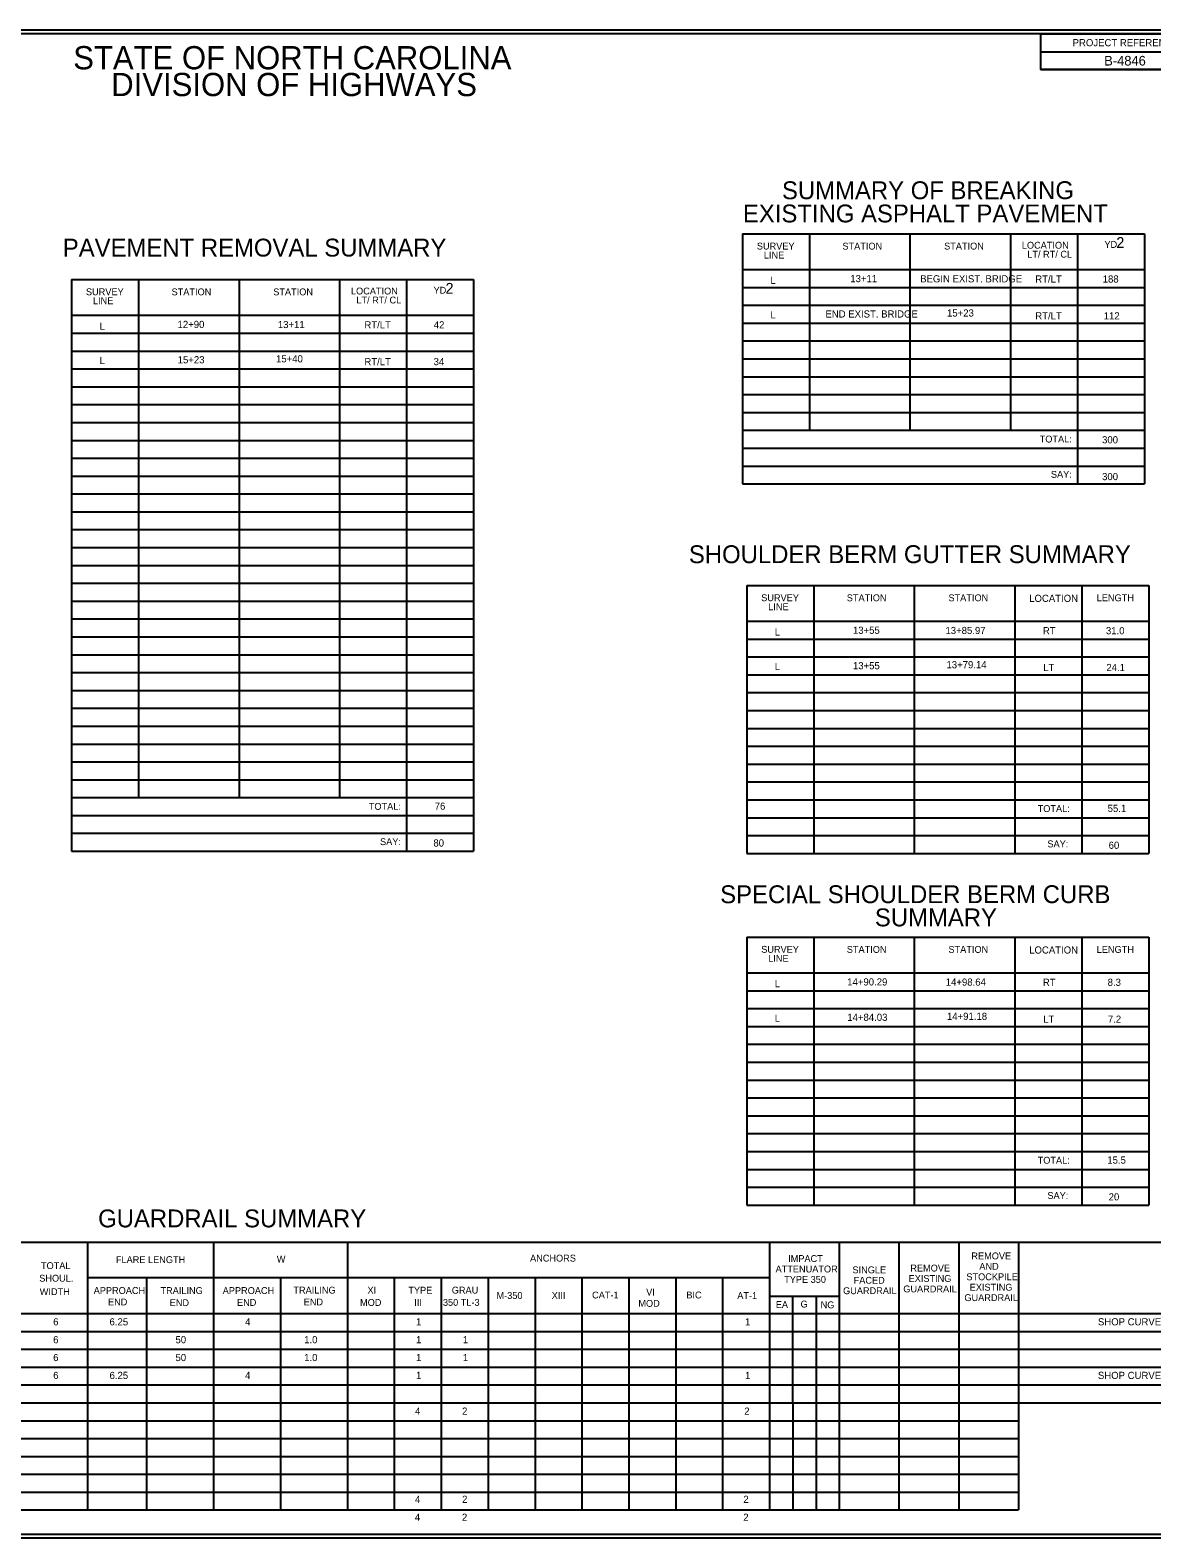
# Model space of a CAD drawing. Extents: x 573895.7 to 573936.5, y -53270.1 to -53245.1.
# Drawn here: x 573912.43 to 573928.13, y -53268.14 to -53247.04 of the extents above; entities that cross this region are included whole.
import ezdxf

# ---------------------------------------------------------------- set-up
doc = ezdxf.new("R2010")
doc.units = 0
for name, color, linetype in [('Sheet Data Field CELL', 7, 'Continuous'), ('Sheet Plot Border Inside CELL', 7, 'Continuous'), ('Sheet Summary Combination CELL', 7, 'Continuous'), ('Sheet Summary Combination Grid CELL', 7, 'Continuous')]:
    doc.layers.add(name, color=color, linetype=linetype)

msp = doc.modelspace()

# ---------------------------------------------------------------- linework, layer by layer
at = {"layer": 'Sheet Plot Border Inside CELL'}
msp.add_lwpolyline([(573930.827, -53247.042), (573897.497, -53247.042), (573897.497, -53268.144), (573930.827, -53268.144)], close=True, dxfattribs=at)
at = {"layer": 'Sheet Summary Combination CELL'}
for p, q in [((573926.576, -53247.344), (573930.577, -53247.344)), ((573926.576, -53247.594), (573930.577, -53247.594)), ((573925.222, -53249.893), (573925.222, -53249.893)), ((573925.347, -53249.895), (573925.347, -53249.895)), ((573925.528, -53249.891), (573925.528, -53249.891)), ((573925.64, -53249.893), (573925.64, -53249.893)), ((573915.832, -53250.534), (573915.832, -53250.534)), ((573915.957, -53250.536), (573915.957, -53250.536)), ((573916.138, -53250.532), (573916.138, -53250.532)), ((573916.25, -53250.534), (573916.25, -53250.534))]:
    msp.add_line(p, q, dxfattribs=at)
for points in [[(573930.577, -53247.093), (573900.577, -53247.093), (573900.577, -53268.093), (573930.577, -53268.093)], [(573926.576, -53247.093), (573930.577, -53247.093), (573930.577, -53247.594), (573926.576, -53247.594)]]:
    msp.add_lwpolyline(points, close=True, dxfattribs=at)
at = {"layer": 'Sheet Summary Combination Grid CELL'}
for p, q in [((573922.397, -53249.892), (573928.024, -53249.892)), ((573922.397, -53249.892), (573922.397, -53253.392)), ((573923.335, -53249.892), (573923.335, -53252.642)), ((573924.742, -53249.892), (573924.742, -53252.642)), ((573926.148, -53249.892), (573926.148, -53252.642)), ((573927.086, -53249.892), (573927.086, -53253.392)), ((573928.024, -53249.892), (573928.024, -53253.392)), ((573922.397, -53250.392), (573928.024, -53250.392)), ((573913.007, -53250.533), (573918.634, -53250.533)), ((573913.007, -53250.533), (573913.007, -53258.533)), ((573913.945, -53250.533), (573913.945, -53257.783)), ((573915.352, -53250.533), (573915.352, -53257.783)), ((573916.758, -53250.533), (573916.758, -53257.783)), ((573917.696, -53250.533), (573917.696, -53258.533)), ((573918.634, -53250.533), (573918.634, -53258.533)), ((573922.397, -53250.642), (573928.024, -53250.642)), ((573922.397, -53250.892), (573928.024, -53250.892)), ((573913.007, -53251.033), (573918.634, -53251.033)), ((573913.007, -53251.283), (573918.634, -53251.283)), ((573922.397, -53251.142), (573928.024, -53251.142)), ((573922.397, -53251.392), (573928.024, -53251.392)), ((573913.007, -53251.533), (573918.634, -53251.533)), ((573922.397, -53251.642), (573928.024, -53251.642)), ((573913.007, -53251.783), (573918.634, -53251.783)), ((573922.397, -53251.892), (573928.024, -53251.892)), ((573913.007, -53252.033), (573918.634, -53252.033)), ((573922.397, -53252.142), (573928.024, -53252.142)), ((573913.007, -53252.283), (573918.634, -53252.283)), ((573913.007, -53252.533), (573918.634, -53252.533)), ((573922.397, -53252.392), (573928.024, -53252.392)), ((573913.007, -53252.783), (573918.634, -53252.783)), ((573922.397, -53252.642), (573928.024, -53252.642)), ((573922.397, -53252.892), (573928.024, -53252.892)), ((573913.007, -53253.033), (573918.634, -53253.033)), ((573922.397, -53253.142), (573928.024, -53253.142)), ((573913.007, -53253.283), (573918.634, -53253.283)), ((573922.397, -53253.392), (573928.024, -53253.392)), ((573913.007, -53253.533), (573918.634, -53253.533)), ((573913.007, -53253.783), (573918.634, -53253.783)), ((573913.007, -53254.033), (573918.634, -53254.033)), ((573913.007, -53254.283), (573918.634, -53254.283)), ((573913.007, -53254.533), (573918.634, -53254.533)), ((573913.007, -53254.783), (573918.634, -53254.783)), ((573922.458, -53254.814), (573928.085, -53254.814)), ((573922.458, -53254.814), (573922.458, -53258.564)), ((573923.396, -53254.814), (573923.396, -53258.564)), ((573924.803, -53254.814), (573924.803, -53258.564)), ((573926.209, -53254.814), (573926.209, -53258.564)), ((573927.147, -53254.814), (573927.147, -53258.564)), ((573928.085, -53254.814), (573928.085, -53258.564)), ((573913.007, -53255.033), (573918.634, -53255.033)), ((573913.007, -53255.283), (573918.634, -53255.283)), ((573922.458, -53255.314), (573928.085, -53255.314)), ((573913.007, -53255.533), (573918.634, -53255.533)), ((573922.458, -53255.564), (573928.085, -53255.564)), ((573913.007, -53255.783), (573918.634, -53255.783)), ((573922.458, -53255.814), (573928.085, -53255.814)), ((573913.007, -53256.033), (573918.634, -53256.033)), ((573922.458, -53256.064), (573928.085, -53256.064)), ((573913.007, -53256.283), (573918.634, -53256.283)), ((573922.458, -53256.314), (573928.085, -53256.314)), ((573913.007, -53256.533), (573918.634, -53256.533)), ((573922.458, -53256.564), (573928.085, -53256.564)), ((573913.007, -53256.783), (573918.634, -53256.783)), ((573922.458, -53256.814), (573928.085, -53256.814)), ((573913.007, -53257.033), (573918.634, -53257.033)), ((573922.458, -53257.064), (573928.085, -53257.064)), ((573913.007, -53257.283), (573918.634, -53257.283)), ((573922.458, -53257.314), (573928.085, -53257.314)), ((573913.007, -53257.533), (573918.634, -53257.533)), ((573922.458, -53257.564), (573928.085, -53257.564)), ((573913.007, -53257.783), (573918.634, -53257.783)), ((573922.458, -53257.814), (573928.085, -53257.814)), ((573913.007, -53258.033), (573918.634, -53258.033)), ((573922.458, -53258.064), (573928.085, -53258.064)), ((573913.007, -53258.283), (573918.634, -53258.283)), ((573922.458, -53258.314), (573928.085, -53258.314)), ((573913.007, -53258.533), (573918.634, -53258.533)), ((573922.458, -53258.564), (573928.085, -53258.564)), ((573922.458, -53259.736), (573928.085, -53259.736)), ((573922.458, -53259.736), (573922.458, -53263.486)), ((573923.396, -53259.736), (573923.396, -53263.486)), ((573924.803, -53259.736), (573924.803, -53263.486)), ((573926.209, -53259.736), (573926.209, -53263.486)), ((573927.147, -53259.736), (573927.147, -53263.486)), ((573928.085, -53259.736), (573928.085, -53263.486)), ((573922.458, -53260.236), (573928.085, -53260.236)), ((573922.458, -53260.486), (573928.085, -53260.486)), ((573922.458, -53260.736), (573928.085, -53260.736)), ((573922.458, -53260.986), (573928.085, -53260.986)), ((573922.458, -53261.236), (573928.085, -53261.236)), ((573922.458, -53261.486), (573928.085, -53261.486)), ((573922.458, -53261.736), (573928.085, -53261.736)), ((573922.458, -53261.986), (573928.085, -53261.986)), ((573922.458, -53262.236), (573928.085, -53262.236)), ((573922.458, -53262.486), (573928.085, -53262.486)), ((573922.458, -53262.736), (573928.085, -53262.736)), ((573922.458, -53262.986), (573928.085, -53262.986)), ((573922.458, -53263.236), (573928.085, -53263.236)), ((573922.458, -53263.486), (573928.085, -53263.486)), ((573900.577, -53264.004), (573930.577, -53264.004)), ((573913.233, -53264.004), (573913.233, -53267.754)), ((573914.995, -53264.004), (573914.995, -53267.754)), ((573916.87, -53264.004), (573916.87, -53267.754)), ((573922.776, -53264.004), (573922.776, -53267.754)), ((573923.753, -53264.004), (573923.753, -53267.754)), ((573924.589, -53264.004), (573924.589, -53267.754)), ((573925.425, -53264.004), (573925.425, -53267.754)), ((573926.262, -53264.004), (573926.262, -53267.754)), ((573922.776, -53264.504), (573913.233, -53264.504)), ((573914.057, -53264.504), (573914.057, -53267.754)), ((573915.932, -53264.504), (573915.932, -53267.754)), ((573917.526, -53264.504), (573917.526, -53267.754)), ((573918.182, -53264.504), (573918.182, -53267.754)), ((573918.839, -53264.504), (573918.839, -53267.754)), ((573919.495, -53264.504), (573919.495, -53267.754)), ((573920.151, -53264.504), (573920.151, -53267.754)), ((573920.807, -53264.504), (573920.807, -53267.754)), ((573921.464, -53264.504), (573921.464, -53267.754)), ((573922.12, -53264.504), (573922.12, -53267.754)), ((573922.776, -53264.759), (573923.748, -53264.759)), ((573923.101, -53264.759), (573923.103, -53267.754)), ((573923.428, -53264.759), (573923.43, -53267.754)), ((573900.577, -53265.004), (573930.577, -53265.004)), ((573900.577, -53265.254), (573930.577, -53265.254)), ((573900.577, -53265.504), (573930.577, -53265.504)), ((573900.577, -53265.754), (573930.577, -53265.754)), ((573900.577, -53266.004), (573930.577, -53266.004)), ((573900.577, -53266.254), (573930.577, -53266.254)), ((573900.577, -53266.504), (573926.262, -53266.504)), ((573900.577, -53266.754), (573926.262, -53266.754)), ((573900.577, -53267.004), (573926.262, -53267.004)), ((573900.577, -53267.254), (573926.262, -53267.254)), ((573900.577, -53267.504), (573926.262, -53267.504)), ((573900.577, -53267.754), (573926.262, -53267.754))]:
    msp.add_line(p, q, dxfattribs=at)

# ---------------------------------------------------------------- texts
at = {"layer": 'Sheet Data Field CELL'}
msp.add_text('B-4846', height=0.135, dxfattribs=at).set_placement((573927.462, -53247.537))
at = {"layer": 'Sheet Summary Combination CELL'}
for s, height, p in [('STATE OF NORTH CAROLINA', 0.325, (573913.032, -53247.59)), ('PROJECT REFERENCE NO.', 0.1, (573927.02, -53247.267)), ('DIVISION OF HIGHWAYS', 0.325, (573913.564, -53247.965)), ('SURVEY', 0.096, (573922.6, -53250.112)), ('STATION', 0.096, (573923.798, -53250.113)), ('STATION', 0.096, (573925.221, -53250.112)), ('LOCATION', 0.096, (573926.309, -53250.1)), ('LINE', 0.096, (573922.698, -53250.238)), ('LT/ RT/ CL', 0.096, (573926.385, -53250.226)), ('RT/LT', 0.1, (573926.497, -53250.575)), ('188', 0.1, (573927.441, -53250.575)), ('SURVEY', 0.096, (573913.21, -53250.752)), ('STATION', 0.096, (573914.408, -53250.753)), ('STATION', 0.096, (573915.831, -53250.753)), ('LOCATION', 0.096, (573916.919, -53250.741)), ('LINE', 0.096, (573913.308, -53250.878)), ('LT/ RT/ CL', 0.096, (573916.995, -53250.867)), ('RT/LT', 0.1, (573926.497, -53251.09)), ('112', 0.1, (573927.455, -53251.09)), ('RT/LT', 0.1, (573917.107, -53251.216)), ('42', 0.1, (573918.078, -53251.216)), ('RT/LT', 0.1, (573917.107, -53251.731)), ('34', 0.1, (573918.076, -53251.731)), ('TOTAL:', 0.096, (573926.559, -53252.813)), ('300', 0.1, (573927.432, -53252.825)), ('SAY:', 0.096, (573926.716, -53253.307)), ('300', 0.1, (573927.432, -53253.34)), ('SURVEY', 0.096, (573922.661, -53255.034)), ('LINE', 0.096, (573922.759, -53255.16)), ('STATION', 0.096, (573923.859, -53255.035)), ('STATION', 0.096, (573925.282, -53255.035)), ('LOCATION', 0.1, (573926.412, -53255.044)), ('LENGTH', 0.096, (573927.357, -53255.035)), ('RT', 0.1, (573926.603, -53255.497)), ('31.0', 0.1, (573927.486, -53255.497)), ('LT', 0.1, (573926.608, -53256.012)), ('24.1', 0.1, (573927.492, -53256.012)), ('TOTAL:', 0.096, (573917.169, -53257.954)), ('76', 0.1, (573918.091, -53257.953)), ('TOTAL:', 0.096, (573926.53, -53257.985)), ('55.1', 0.1, (573927.51, -53257.984)), ('SAY:', 0.096, (573917.326, -53258.448)), ('80', 0.1, (573918.073, -53258.468)), ('SAY:', 0.096, (573926.667, -53258.479)), ('60', 0.1, (573927.524, -53258.5)), ('SURVEY', 0.096, (573922.661, -53259.955)), ('STATION', 0.096, (573923.859, -53259.956)), ('STATION', 0.096, (573925.282, -53259.956)), ('LOCATION', 0.1, (573926.412, -53259.966)), ('LENGTH', 0.096, (573927.357, -53259.956)), ('LINE', 0.096, (573922.759, -53260.081)), ('RT', 0.1, (573926.603, -53260.418)), ('8.3', 0.1, (573927.51, -53260.418)), ('LT', 0.1, (573926.608, -53260.934)), ('7.2', 0.1, (573927.513, -53260.934)), ('TOTAL:', 0.096, (573926.53, -53262.907)), ('15.5', 0.1, (573927.505, -53262.906)), ('SAY:', 0.096, (573926.667, -53263.401)), ('20', 0.1, (573927.524, -53263.421)), ('GUARDRAIL SUMMARY', 0.25, (573913.38, -53263.798)), ('ANCHORS', 0.096, (573919.426, -53264.277)), ('IMPACT', 0.096, (573923.038, -53264.283)), ('REMOVE', 0.096, (573925.603, -53264.246)), ('TOTAL', 0.096, (573912.58, -53264.382)), ('FLARE LENGTH', 0.096, (573913.629, -53264.298)), ('W', 0.096, (573915.881, -53264.29)), ('ATTENUATOR', 0.096, (573922.862, -53264.429)), ('SINGLE', 0.096, (573923.938, -53264.441)), ('REMOVE', 0.096, (573924.748, -53264.416)), ('AND', 0.096, (573925.714, -53264.392)), ('SHOUL.', 0.096, (573912.556, -53264.558)), ('TYPE 350', 0.096, (573922.982, -53264.575)), ('FACED', 0.096, (573923.955, -53264.587)), ('GUARDRAIL', 0.096, (573924.65, -53264.708)), ('EXISTING', 0.096, (573924.724, -53264.562)), ('STOCKPILE', 0.096, (573925.533, -53264.538)), ('EXISTING', 0.096, (573925.579, -53264.684)), ('WIDTH', 0.096, (573912.563, -53264.746)), ('APPROACH', 0.096, (573913.318, -53264.73)), ('END', 0.096, (573913.518, -53264.89)), ('TRAILING', 0.096, (573914.253, -53264.731)), ('END', 0.096, (573914.382, -53264.901)), ('APPROACH', 0.096, (573915.124, -53264.731)), ('END', 0.096, (573915.324, -53264.897)), ('TRAILING', 0.096, (573916.113, -53264.725)), ('END', 0.096, (573916.257, -53264.89)), ('MOD', 0.096, (573917.046, -53264.897)), ('XI', 0.096, (573917.15, -53264.726)), ('TYPE', 0.096, (573917.722, -53264.726)), ('III', 0.096, (573917.805, -53264.897)), ('350 TL-3', 0.096, (573918.206, -53264.896)), ('GRAU', 0.096, (573918.33, -53264.725)), ('M-350', 0.096, (573918.956, -53264.8)), ('XIII', 0.096, (573919.729, -53264.8)), ('CAT-1', 0.096, (573920.294, -53264.793)), ('MOD', 0.096, (573920.942, -53264.91)), ('VI', 0.096, (573921.051, -53264.752)), ('BIC', 0.096, (573921.613, -53264.793)), ('AT-1', 0.096, (573922.326, -53264.801)), ('G', 0.096, (573923.212, -53264.92)), ('GUARDRAIL', 0.096, (573923.807, -53264.733)), ('GUARDRAIL', 0.096, (573925.505, -53264.83)), ('EA', 0.096, (573922.865, -53264.927)), ('NG', 0.096, (573923.493, -53264.931)), ('6', 0.1, (573912.751, -53265.17)), ('6.25', 0.1, (573913.54, -53265.17)), ('4', 0.1, (573915.437, -53265.17)), ('1', 0.1, (573917.83, -53265.17)), ('1', 0.1, (573922.435, -53265.17)), ('SHOP CURVED AT DRIVEWAY ENTRANCE', 0.1, (573927.374, -53265.17)), ('6', 0.1, (573912.751, -53265.42)), ('50', 0.1, (573914.463, -53265.42)), ('1.0', 0.1, (573916.264, -53265.42)), ('1', 0.1, (573917.83, -53265.42)), ('1', 0.1, (573918.486, -53265.42)), ('6', 0.1, (573912.751, -53265.67)), ('50', 0.1, (573914.463, -53265.67)), ('1.0', 0.1, (573916.264, -53265.67)), ('1', 0.1, (573917.83, -53265.67)), ('1', 0.1, (573918.486, -53265.67)), ('6', 0.1, (573912.751, -53265.92)), ('6.25', 0.1, (573913.54, -53265.92)), ('4', 0.1, (573915.437, -53265.92)), ('1', 0.1, (573917.83, -53265.92)), ('1', 0.1, (573922.435, -53265.92)), ('SHOP CURVED AT DRIVEWAY ENTRANCE', 0.1, (573927.374, -53265.92)), ('4', 0.1, (573917.816, -53266.42)), ('2', 0.1, (573918.474, -53266.42)), ('2', 0.1, (573922.424, -53266.42)), ('4', 0.1, (573917.816, -53267.654)), ('2', 0.1, (573918.474, -53267.654)), ('2', 0.1, (573922.411, -53267.654)), ('4', 0.1, (573917.813, -53267.905)), ('2', 0.1, (573918.472, -53267.905)), ('2', 0.1, (573922.41, -53267.905))]:
    msp.add_text(s, height=height, dxfattribs=at).set_placement(p)
for s, p in [('SUMMARY OF BREAKING', (573922.952, -53249.408)), ('EXISTING ASPHALT PAVEMENT', (573922.405, -53249.733)), ('PAVEMENT REMOVAL SUMMARY', (573912.886, -53250.211)), ('SHOULDER BERM GUTTER SUMMARY', (573921.649, -53254.502)), ('SPECIAL SHOULDER BERM CURB', (573922.087, -53259.261)), ('SUMMARY', (573924.252, -53259.585))]:
    msp.add_text(s, height=0.25, rotation=0.0119, dxfattribs=at).set_placement(p)
at = {"layer": 'Sheet Summary Combination Grid CELL'}
for s, height, p in [('YD', 0.096, (573927.465, -53250.089)), ('2', 0.15, (573927.632, -53250.089)), ('13+11', 0.1, (573923.908, -53250.569)), ('BEGIN EXIST. BRIDGE', 0.1, (573924.886, -53250.572)), ('YD', 0.096, (573918.075, -53250.73)), ('2', 0.15, (573918.243, -53250.73)), ('L', 0.1, (573922.79, -53250.594)), ('L', 0.1, (573922.79, -53251.075)), ('END EXIST. BRIDGE', 0.1, (573923.56, -53251.064)), ('15+23', 0.1, (573925.262, -53251.05)), ('L', 0.1, (573913.401, -53251.235)), ('12+90', 0.1, (573914.492, -53251.21)), ('13+11', 0.1, (573915.896, -53251.212)), ('L', 0.1, (573913.401, -53251.716)), ('15+23', 0.1, (573914.494, -53251.705)), ('15+40', 0.1, (573915.87, -53251.691)), ('L', 0.1, (573922.851, -53255.516)), ('13+55', 0.1, (573923.945, -53255.491)), ('13+85.97', 0.1, (573925.24, -53255.494)), ('L', 0.1, (573922.851, -53255.997)), ('13+55', 0.1, (573923.945, -53255.987)), ('13+79.14', 0.1, (573925.254, -53255.973)), ('L', 0.1, (573922.851, -53260.438)), ('14+90.29', 0.1, (573923.865, -53260.413)), ('14+98.64', 0.1, (573925.244, -53260.415)), ('14+84.03', 0.1, (573923.866, -53260.908)), ('14+91.18', 0.1, (573925.261, -53260.894)), ('L', 0.1, (573922.851, -53260.919))]:
    msp.add_text(s, height=height, dxfattribs=at).set_placement(p)

doc.saveas('drawing.dxf')
